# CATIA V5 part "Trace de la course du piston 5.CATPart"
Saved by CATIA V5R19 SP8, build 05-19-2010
Part number: Trace de la course du piston 5
Bounding box of the stored display mesh (mm): x 0 to 0, y 152.5 to 152.5, z 427.392 to 467.408
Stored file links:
  F:\Colonel\Synthèse IAO\Optimisé\Trace de la course du piston 5.CATPart
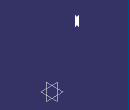
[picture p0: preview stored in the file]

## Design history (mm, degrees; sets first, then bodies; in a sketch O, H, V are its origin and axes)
Set1
  Point1: (0, 152.5, 433.3678)
  Point2: (0, 152.5, 449.996)
  Point3: (0, 152.5, 448.5083)
  Point4: (0, 152.5, 446.9753)
  Point5: (0, 152.5, 445.4073)
  Point6: (0, 152.5, 443.8165)
  Point7: (0, 152.5, 442.2172)
  Point8: (0, 152.5, 440.6254)
  Point9: (0, 152.5, 439.0578)
  Point10: (0, 152.5, 437.5317)
  Point11: (0, 152.5, 436.0641)
  Point12: (0, 152.5, 434.6711)
  Point13: (0, 152.5, 433.3678)
  Point14: (0, 152.5, 432.1675)
  Point15: (0, 152.5, 431.082)
  Point16: (0, 152.5, 430.1215)
  Point17: (0, 152.5, 429.2947)
  Point18: (0, 152.5, 428.6088)
  Point19: (0, 152.5, 428.0703)
  Point20: (0, 152.5, 427.6848)
  Point21: (0, 152.5, 427.4575)
  Point22: (0, 152.5, 427.3936)
  Point23: (0, 152.5, 427.4981)
  Point24: (0, 152.5, 427.7759)
  Point25: (0, 152.5, 428.2321)
  Point26: (0, 152.5, 428.8714)
  Point27: (0, 152.5, 429.6979)
  Point28: (0, 152.5, 430.7147)
  Point29: (0, 152.5, 431.9231)
  Point30: (0, 152.5, 433.3219)
  Point31: (0, 152.5, 434.9062)
  Point32: (0, 152.5, 436.6667)
  Point33: (0, 152.5, 438.5889)
  Point34: (0, 152.5, 440.652)
  Point35: (0, 152.5, 442.8292)
  Point36: (0, 152.5, 445.0877)
  Point37: (0, 152.5, 447.3901)
  Point38: (0, 152.5, 449.6958)
  Point39: (0, 152.5, 451.9633)
  Point40: (0, 152.5, 454.1527)
  Point41: (0, 152.5, 456.2277)
  Point42: (0, 152.5, 458.1579)
  Point43: (0, 152.5, 459.9195)
  Point44: (0, 152.5, 461.4962)
  Point45: (0, 152.5, 462.8787)
  Point46: (0, 152.5, 464.064)
  Point47: (0, 152.5, 465.0545)
  Point48: (0, 152.5, 465.8563)
  Point49: (0, 152.5, 466.4787)
  Point50: (0, 152.5, 466.9326)
  Point51: (0, 152.5, 467.2299)
  Point52: (0, 152.5, 467.3829)
  Point53: (0, 152.5, 467.4036)
  Point54: (0, 152.5, 467.3038)
  Point55: (0, 152.5, 467.0945)
  Point56: (0, 152.5, 466.7859)
  Point57: (0, 152.5, 466.3872)
  Point58: (0, 152.5, 465.907)
  Point59: (0, 152.5, 465.3526)
  Point60: (0, 152.5, 464.7304)
  Point61: (0, 152.5, 464.0456)
  Point62: (0, 152.5, 463.3022)
  Point63: (0, 152.5, 462.5032)
  Point64: (0, 152.5, 461.6503)
  Point65: (0, 152.5, 460.7441)
  Point66: (0, 152.5, 459.7842)
  Point67: (0, 152.5, 458.7693)
  Point68: (0, 152.5, 457.6978)
  Point69: (0, 152.5, 456.5674)
  Point70: (0, 152.5, 455.3763)
  Point71: (0, 152.5, 454.1231)
  Point72: (0, 152.5, 452.8076)
  Point73: (0, 152.5, 451.4308)
  Point74: (0, 152.5, 449.996)
  Point75: (0, 152.5, 448.5083)
  Point76: (0, 152.5, 446.9753)
  Point77: (0, 152.5, 445.4073)
  Point78: (0, 152.5, 443.8165)
  Point79: (0, 152.5, 442.2172)
  Point80: (0, 152.5, 440.6254)
  Point81: (0, 152.5, 439.0578)
  Point82: (0, 152.5, 437.5317)
  Point83: (0, 152.5, 436.0641)
  Point84: (0, 152.5, 434.6711)
  Point85: (0, 152.5, 433.3678)
  Point86: (0, 152.5, 432.1675)
  Point87: (0, 152.5, 431.082)
  Point88: (0, 152.5, 430.1215)
  Point89: (0, 152.5, 429.2947)
  Point90: (0, 152.5, 428.6088)
  Point91: (0, 152.5, 428.0703)
  Point92: (0, 152.5, 427.6848)
  Point93: (0, 152.5, 427.4575)
  Point94: (0, 152.5, 427.3936)
  Point95: (0, 152.5, 427.4981)
  Point96: (0, 152.5, 427.7759)
  Point97: (0, 152.5, 428.2321)
  Point98: (0, 152.5, 428.8714)
  Point99: (0, 152.5, 429.6979)
  Point100: (0, 152.5, 430.7147)
  Point101: (0, 152.5, 431.9231)
  Point102: (0, 152.5, 433.3219)
  Point103: (0, 152.5, 434.9062)
  Point104: (0, 152.5, 436.6667)
  Point105: (0, 152.5, 438.5889)
  Point106: (0, 152.5, 440.652)
  Point107: (0, 152.5, 442.8292)
  Point108: (0, 152.5, 445.0877)
  Point109: (0, 152.5, 447.3901)
  Point110: (0, 152.5, 449.6958)
  Point111: (0, 152.5, 451.9633)
  Point112: (0, 152.5, 454.1527)
  Point113: (0, 152.5, 456.2277)
  Point114: (0, 152.5, 458.1579)
  Point115: (0, 152.5, 459.9195)
  Point116: (0, 152.5, 461.4962)
  Point117: (0, 152.5, 462.8787)
  Point118: (0, 152.5, 464.064)
  Point119: (0, 152.5, 465.0545)
  Point120: (0, 152.5, 465.8563)
  Point121: (0, 152.5, 466.4787)
  Point122: (0, 152.5, 466.9326)
  Point123: (0, 152.5, 467.2299)
  Point124: (0, 152.5, 467.3829)
  Point125: (0, 152.5, 467.4036)
  Point126: (0, 152.5, 467.3038)
  Point127: (0, 152.5, 467.0945)
  Point128: (0, 152.5, 466.7859)
  Point129: (0, 152.5, 466.3872)
  Point130: (0, 152.5, 465.907)
  Point131: (0, 152.5, 465.3526)
  Point132: (0, 152.5, 464.7304)
  Point133: (0, 152.5, 464.0456)
  Point134: (0, 152.5, 463.3022)
  Point135: (0, 152.5, 462.5032)
  Point136: (0, 152.5, 461.6503)
  Point137: (0, 152.5, 460.7441)
  Point138: (0, 152.5, 459.7842)
  Point139: (0, 152.5, 458.7693)
  Point140: (0, 152.5, 457.6978)
  Point141: (0, 152.5, 456.5674)
  Point142: (0, 152.5, 455.3763)
  Point143: (0, 152.5, 454.1231)
  Point144: (0, 152.5, 452.8076)
  Point145: (0, 152.5, 451.4308)
  Point146: (0, 152.5, 449.996)
  Point147: (0, 152.5, 448.5083)
  Point148: (0, 152.5, 446.9753)
  Point149: (0, 152.5, 445.4073)
  Point150: (0, 152.5, 443.8165)
  Point151: (0, 152.5, 442.2172)
  Point152: (0, 152.5, 440.6254)
  Point153: (0, 152.5, 439.0578)
  Point154: (0, 152.5, 437.5317)
  Point155: (0, 152.5, 436.0641)
  Point156: (0, 152.5, 434.6711)
  Point157: (0, 152.5, 433.3678)
  Point158: (0, 152.5, 432.1675)
  Point159: (0, 152.5, 431.082)
  Point160: (0, 152.5, 430.1215)
  Point161: (0, 152.5, 429.2947)
  Point162: (0, 152.5, 428.6088)
  Point163: (0, 152.5, 428.0703)
  Point164: (0, 152.5, 427.6848)
  Point165: (0, 152.5, 427.4575)
  Point166: (0, 152.5, 427.3936)
  Point167: (0, 152.5, 427.4981)
  Point168: (0, 152.5, 427.7759)
  Point169: (0, 152.5, 428.2321)
  Point170: (0, 152.5, 428.8714)
  Point171: (0, 152.5, 429.6979)
  Point172: (0, 152.5, 430.7147)
  Point173: (0, 152.5, 431.9231)
  Point174: (0, 152.5, 433.3219)
  Point175: (0, 152.5, 434.9062)
  Point176: (0, 152.5, 436.6667)
  Point177: (0, 152.5, 438.5889)
  Point178: (0, 152.5, 440.652)
  Point179: (0, 152.5, 442.8292)
  Point180: (0, 152.5, 445.0877)
  Point181: (0, 152.5, 447.3901)
  Point182: (0, 152.5, 449.6958)
  Point183: (0, 152.5, 451.9633)
  Point184: (0, 152.5, 454.1527)
  Point185: (0, 152.5, 456.2277)
  Point186: (0, 152.5, 458.1579)
  Point187: (0, 152.5, 459.9195)
  Point188: (0, 152.5, 461.4962)
  Point189: (0, 152.5, 462.8787)
  Point190: (0, 152.5, 464.064)
  Point191: (0, 152.5, 465.0545)
  Point192: (0, 152.5, 465.8563)
  Point193: (0, 152.5, 466.4787)
  Point194: (0, 152.5, 466.9326)
  Point195: (0, 152.5, 467.2299)
  Point196: (0, 152.5, 467.3829)
  Point197: (0, 152.5, 467.4036)
  Point198: (0, 152.5, 467.3038)
  Point199: (0, 152.5, 467.0945)
  Point200: (0, 152.5, 466.7859)
  Point201: (0, 152.5, 466.3872)
  Point202: (0, 152.5, 465.907)
  Point203: (0, 152.5, 465.3526)
  Point204: (0, 152.5, 464.7304)
  Point205: (0, 152.5, 464.0456)
  Point206: (0, 152.5, 463.3022)
  Point207: (0, 152.5, 462.5032)
  Point208: (0, 152.5, 461.6503)
  Point209: (0, 152.5, 460.7441)
  Point210: (0, 152.5, 459.7842)
  Point211: (0, 152.5, 458.7693)
  Point212: (0, 152.5, 457.6978)
  Point213: (0, 152.5, 456.5674)
  Point214: (0, 152.5, 455.3763)
  Point215: (0, 152.5, 454.1231)
  Point216: (0, 152.5, 452.8076)
  Point217: (0, 152.5, 451.4308)
  Point218: (0, 152.5, 449.996)
  Point219: (0, 152.5, 448.5082)
  Point220: (0, 152.5, 446.9753)
  Point221: (0, 152.5, 445.4073)
  Point222: (0, 152.5, 443.8165)
  Point223: (0, 152.5, 442.2172)
  Point224: (0, 152.5, 440.6254)
  Point225: (0, 152.5, 439.0578)
  Point226: (0, 152.5, 437.5317)
  Point227: (0, 152.5, 436.0641)
  Point228: (0, 152.5, 434.6711)
  Point229: (0, 152.5, 433.3678)
  Point230: (0, 152.5, 432.1675)
  Point231: (0, 152.5, 431.082)
  Point232: (0, 152.5, 430.1215)
  Point233: (0, 152.5, 429.2947)
  Point234: (0, 152.5, 428.6088)
  Point235: (0, 152.5, 428.0703)
  Point236: (0, 152.5, 427.6848)
  Point237: (0, 152.5, 427.4575)
  Point238: (0, 152.5, 427.3936)
  Point239: (0, 152.5, 427.4981)
  Point240: (0, 152.5, 427.7759)
  Point241: (0, 152.5, 428.2321)
  Point242: (0, 152.5, 428.8714)
  Point243: (0, 152.5, 429.6979)
  Point244: (0, 152.5, 430.7147)
  Point245: (0, 152.5, 431.9231)
  Point246: (0, 152.5, 433.3219)
  Point247: (0, 152.5, 434.9062)
  Point248: (0, 152.5, 436.6667)
  Point249: (0, 152.5, 438.5889)
  Point250: (0, 152.5, 440.652)
  Point251: (0, 152.5, 442.8292)
  Point252: (0, 152.5, 445.0877)
  Point253: (0, 152.5, 447.3901)
  Point254: (0, 152.5, 449.6958)
  Point255: (0, 152.5, 451.9633)
  Point256: (0, 152.5, 454.1527)
  Point257: (0, 152.5, 456.2277)
  Point258: (0, 152.5, 458.1579)
  Point259: (0, 152.5, 459.9195)
  Point260: (0, 152.5, 461.4962)
  Point261: (0, 152.5, 462.8787)
  Point262: (0, 152.5, 464.064)
  Point263: (0, 152.5, 465.0545)
  Point264: (0, 152.5, 465.8563)
  Point265: (0, 152.5, 466.4787)
  Point266: (0, 152.5, 466.9326)
  Point267: (0, 152.5, 467.2299)
  Point268: (0, 152.5, 467.3829)
  Point269: (0, 152.5, 467.4036)
  Point270: (0, 152.5, 467.3038)
  Point271: (0, 152.5, 467.0945)
  Point272: (0, 152.5, 466.7859)
  Point273: (0, 152.5, 466.3872)
  Point274: (0, 152.5, 465.907)
  Point275: (0, 152.5, 465.3526)
  Point276: (0, 152.5, 464.7304)
  Point277: (0, 152.5, 464.0456)
  Point278: (0, 152.5, 463.3022)
  Point279: (0, 152.5, 462.5032)
  Point280: (0, 152.5, 461.6503)
  Point281: (0, 152.5, 460.7441)
  Point282: (0, 152.5, 459.7842)
  Point283: (0, 152.5, 458.7693)
  Point284: (0, 152.5, 457.6978)
  Point285: (0, 152.5, 456.5674)
  Point286: (0, 152.5, 455.3763)
  Point287: (0, 152.5, 454.1231)
  Point288: (0, 152.5, 452.8076)
  Point289: (0, 152.5, 451.4308)
  Point290: (0, 152.5, 449.996)
  Point291: (0, 152.5, 448.5082)
  Point292: (0, 152.5, 446.9753)
  Point293: (0, 152.5, 445.4073)
  Point294: (0, 152.5, 443.8165)
  Point295: (0, 152.5, 442.2172)
  Point296: (0, 152.5, 440.6254)
  Point297: (0, 152.5, 439.0578)
  Point298: (0, 152.5, 437.5317)
  Point299: (0, 152.5, 436.0641)
  Point300: (0, 152.5, 434.6711)
  Point301: (0, 152.5, 433.3678)
  Curve1: Elements (Point1; Point2; Point3; Point4; Point5; Point6; Point7; Point8; Point9; Point10; Point11; Point12; Point13; Point14; Point15; Point16; Point17; Point18; Point19; Point20; Point21; Point22; Point23; Point24; Point25; Point26; Point27; Point28; Point29; Point30; Point31; Point32; Point33; Point34; Point35; Point36; Point37; Point38; Point39; Point40; Point41; Point42; Point43; Point44; Point45; Point46; Point47; Point48; Point49; Point50; Point51; Point52; Point53; Point54; Point55; Point56; Point57; Point58; Point59; Point60; Point61; Point62; Point63; Point64; Point65; Point66; Point67; Point68; Point69; Point70; Point71; Point72; Point73; Point74; Point75; Point76; Point77; Point78; Point79; Point80; Point81; Point82; Point83; Point84; Point85; Point86; Point87; Point88; Point89; Point90; Point91; Point92; Point93; Point94; Point95; Point96; Point97; Point98; Point99; Point100; Point101; Point102; Point103; Point104; Point105; Point106; Point107; Point108; Point109; Point110; Point111; Point112; Point113; Point114; Point115; Point116; Point117; Point118; Point119; Point120; Point121; Point122; Point123; Point124; Point125; Point126; Point127; Point128; Point129; Point130; Point131; Point132; Point133; Point134; Point135; Point136; Point137; Point138; Point139; Point140; Point141; Point142; Point143; Point144; Point145; Point146; Point147; Point148; Point149; Point150; Point151; Point152; Point153; Point154; Point155; Point156; Point157; Point158; Point159; Point160; Point161; Point162; Point163; Point164; Point165; Point166; Point167; Point168; Point169; Point170; Point171; Point172; Point173; Point174; Point175; Point176; Point177; Point178; Point179; Point180; Point181; Point182; Point183; Point184; Point185; Point186; Point187; Point188; Point189; Point190; Point191; Point192; Point193; Point194; Point195; Point196; Point197; Point198; Point199; Point200; Point201; Point202; Point203; Point204; Point205; Point206; Point207; Point208; Point209; Point210; Point211; Point212; Point213; Point214; Point215; Point216; Point217; Point218; Point219; Point220; Point221; Point222; Point223; Point224; Point225; Point226; Point227; Point228; Point229; Point230; Point231; Point232; Point233; Point234; Point235; Point236; Point237; Point238; Point239; Point240; Point241; Point242; Point243; Point244; Point245; Point246; Point247; Point248; Point249; Point250; Point251; Point252; Point253; Point254; Point255; Point256; Point257; Point258; Point259; Point260; Point261; Point262; Point263; Point264; Point265; Point266; Point267; Point268; Point269; Point270; Point271; Point272; Point273; Point274; Point275; Point276; Point277; Point278; Point279; Point280; Point281; Point282; Point283; Point284; Point285; Point286; Point287; Point288; Point289; Point290; Point291; Point292; Point293; Point294; Point295; Point296; Point297; Point298; Point299; Point300; Point301)
Body1 (main body)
